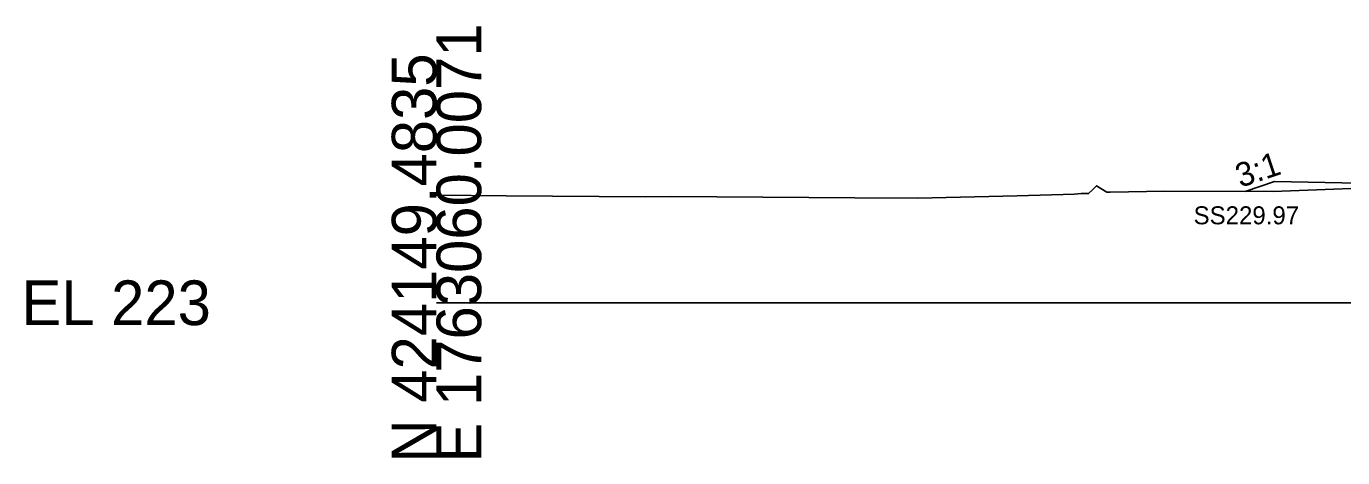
# Model space of a CAD drawing. Extents: x -26 to 3203, y -11010 to 4024.
# Drawn here: x 974.3 to 1056.8, y 3990.3 to 4017.3 of the extents above; entities that cross this region are included whole.
import ezdxf

# ---------------------------------------------------------------- set-up
doc = ezdxf.new("R2010")
doc.units = 0
for name, color, linetype in [('Default', 7, 'Continuous'), ('Exist Cross Section Cell', 7, 'Continuous'), ('Exist XS Ground Line', 7, 'Continuous'), ('Prop CMT Slope Grass', 7, 'Continuous'), ('Prop XS Side Slope Text', 7, 'Continuous'), ('Prop XS SS Elevation Text', 7, 'Continuous'), ('Scratch_Level_0', 7, 'Continuous')]:
    doc.layers.add(name, color=color, linetype=linetype)

msp = doc.modelspace()

# ---------------------------------------------------------------- linework, layer by layer
at = {"layer": 'Exist Cross Section Cell'}
msp.add_line((1000, 4000), (1100, 4000), dxfattribs=at)
at = {"layer": 'Exist XS Ground Line'}
msp.add_lwpolyline([(1000, 4006.725), (1004.368, 4006.696), (1013.097, 4006.637), (1014.671, 4006.645), (1026.203, 4006.566), (1030.142, 4006.551), (1036.369, 4006.697), (1039.956, 4006.802), (1040.375, 4006.836), (1040.85, 4006.832), (1041.09, 4007.063), (1041.352, 4007.323), (1041.983, 4006.922), (1042.2, 4006.915), (1045.613, 4006.981), (1052.415, 4006.973), (1061.083, 4007.293)], dxfattribs=at)
msp.add_lwpolyline([(1000, 4006.725), (1004.368, 4006.696), (1013.097, 4006.637), (1014.671, 4006.645), (1026.203, 4006.566), (1030.142, 4006.551), (1036.369, 4006.697), (1039.956, 4006.802), (1040.375, 4006.836), (1040.85, 4006.832), (1041.09, 4007.063), (1041.352, 4007.323), (1041.983, 4006.922), (1042.2, 4006.915), (1045.613, 4006.981), (1052.415, 4006.973), (1061.083, 4007.293)], dxfattribs=at)
msp.add_lwpolyline([(1000, 4006.725), (1004.368, 4006.696), (1013.097, 4006.637), (1014.671, 4006.645), (1026.203, 4006.566), (1030.142, 4006.551), (1036.369, 4006.697), (1039.956, 4006.802), (1040.375, 4006.836), (1040.85, 4006.832), (1041.09, 4007.063), (1041.352, 4007.323), (1041.983, 4006.922), (1042.2, 4006.915), (1045.613, 4006.981), (1052.415, 4006.973), (1061.083, 4007.293)], dxfattribs=at)
msp.add_lwpolyline([(1000, 4006.725), (1004.368, 4006.696), (1013.097, 4006.637), (1014.671, 4006.645), (1026.203, 4006.566), (1030.142, 4006.551), (1036.369, 4006.697), (1039.956, 4006.802), (1040.375, 4006.836), (1040.85, 4006.832), (1041.09, 4007.063), (1041.352, 4007.323), (1041.983, 4006.922), (1042.2, 4006.915), (1045.613, 4006.981), (1052.415, 4006.973), (1061.083, 4007.293)], dxfattribs=at)
msp.add_lwpolyline([(1000, 4006.725), (1004.368, 4006.696), (1013.097, 4006.637), (1014.671, 4006.645), (1026.203, 4006.566), (1030.142, 4006.551), (1036.369, 4006.697), (1039.956, 4006.802), (1040.375, 4006.836), (1040.85, 4006.832), (1041.09, 4007.063), (1041.352, 4007.323), (1041.983, 4006.922), (1042.2, 4006.915), (1045.613, 4006.981), (1052.415, 4006.973), (1061.083, 4007.293)], dxfattribs=at)
at = {"layer": 'Prop CMT Slope Grass'}
msp.add_lwpolyline([(1061.999, 4007.401), (1052.499, 4007.591), (1050.652, 4006.975)], dxfattribs=at)

# ---------------------------------------------------------------- texts
at = {"layer": 'Default'}
msp.add_text('-', height=0.0001, dxfattribs=at).set_placement((1000, 4000))
at = {"layer": 'Exist Cross Section Cell'}
for s, p in [('E 1763060.0071', (1002.8, 3990)), ('N 424149.4835', (1000, 3990))]:
    msp.add_text(s, height=2.8, rotation=90, dxfattribs=at).set_placement(p)
msp.add_text('EL 223', height=2.8, dxfattribs=at).set_placement((974, 3998.6))
at = {"layer": 'Prop XS Side Slope Text'}
msp.add_text('3:1', height=1.5, rotation=18.43493, dxfattribs=at).set_placement((1050.353, 4007.191))
at = {"layer": 'Prop XS SS Elevation Text'}
msp.add_text('SS229.97', height=1.125, dxfattribs=at).set_placement((1047.425, 4004.912))
at = {"layer": 'Scratch_Level_0'}
for s, p in [('LT_CSLP_Pnt', (1052.401, 4007.581)), ('Exterior Boundary', (1050.493, 4006.965)), ('LT_Slope_Fill', (1050.558, 4006.965))]:
    msp.add_text(s, height=0.02, dxfattribs=at).set_placement(p)

doc.saveas('drawing.dxf')
